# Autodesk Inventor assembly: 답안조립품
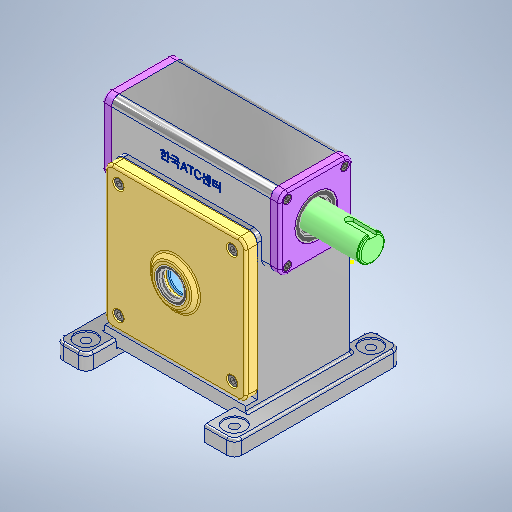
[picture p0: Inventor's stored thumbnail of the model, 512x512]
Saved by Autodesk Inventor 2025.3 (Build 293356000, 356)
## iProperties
Created: 2025-06
Part Number: 답안조립품
Document SubType Name: Assembly
Designer: PC-10
Author: PC-10
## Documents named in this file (13)
- C:\Users\PC-10\Desktop\750603V1015\답안조립품.iam
- C:\Users\PC-10\Desktop\새 폴더\750603V1015\웜 휠\웜 휠.ipt
- C:\Users\PC-10\Desktop\새 폴더\750603V1015\6각 구멍붙이 볼트 M6x12\6각 구멍붙이 볼트 M6x12.ipt
- C:\Users\PC-10\Desktop\새 폴더\750603V1015\6각 구멍붙이 볼트 M8x20\6각 구멍붙이 볼트 M8x20.ipt
- C:\Users\PC-10\Desktop\새 폴더\750603V1015\깊은 홈 볼 베어링 6206\깊은 홈 볼 베어링 6206.ipt
- C:\Users\PC-10\Desktop\새 폴더\750603V1015\깊은 홈 볼 베어링 6209\깊은 홈 볼 베어링 6209.ipt
- C:\Users\PC-10\Desktop\새 폴더\750603V1015\뒷커버\뒷커버.ipt
- C:\Users\PC-10\Desktop\750603V1015\본체.ipt
- C:\Users\PC-10\Desktop\새 폴더\750603V1015\앞커버\앞커버.ipt
- C:\Users\PC-10\Desktop\새 폴더\750603V1015\오일 실 30 42 7\오일 실 30 42 7.ipt
- C:\Users\PC-10\Desktop\새 폴더\750603V1015\오일 실 35 55 11\오일 실 35 55 11.ipt
- C:\Users\PC-10\Desktop\새 폴더\750603V1015\웜 샤프트\웜 샤프트.ipt
- C:\Users\PC-10\Desktop\새 폴더\750603V1015\웜 휠 커버\웜 휠 커버.ipt
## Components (12 placed, 2 different names)
1. 6각 구멍붙이 볼트 M6x12:1
2. 6각 구멍붙이 볼트 M6x12:2
3. 6각 구멍붙이 볼트 M6x12:3
4. 6각 구멍붙이 볼트 M6x12:4
5. 6각 구멍붙이 볼트 M6x12:5
6. 6각 구멍붙이 볼트 M6x12:6
7. 6각 구멍붙이 볼트 M6x12:7
8. 6각 구멍붙이 볼트 M6x12:8
9. 6각 구멍붙이 볼트 M8x20:2
10. 6각 구멍붙이 볼트 M8x20:3
11. 6각 구멍붙이 볼트 M8x20:4
12. 6각 구멍붙이 볼트 M8x20:5
